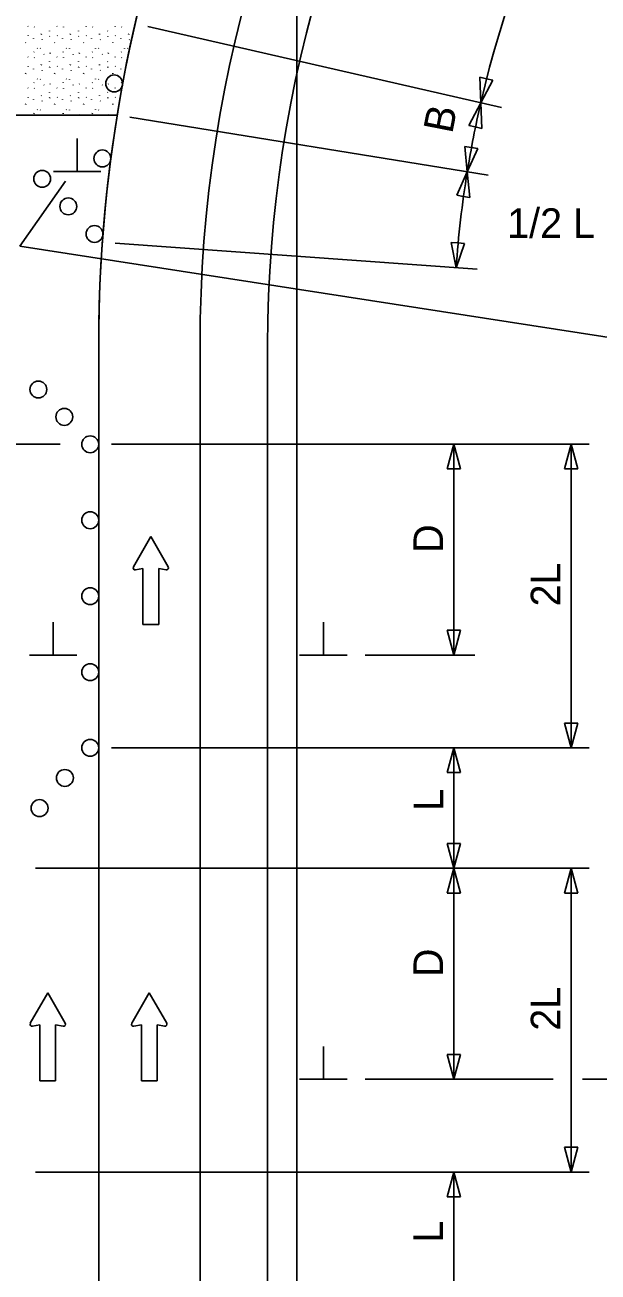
# Model space of a CAD drawing. Extents: x 16731 to 18475, y 7005 to 8303.
# Drawn here: x 16959.8 to 17095.5, y 7670.3 to 7965.9 of the extents above; entities that cross this region are included whole.
import ezdxf

# ---------------------------------------------------------------- set-up
doc = ezdxf.new("R2010")
doc.units = 0
for name, color, linetype in [('ALI_LEGAL_EX', 7, 'Continuous'), ('MT_SCRATCH_LEVEL_A', 7, 'Continuous'), ('MT_SCRATCH_LEVEL_E', 7, 'Continuous'), ('PAVT_EDGE_EX', 7, 'Continuous'), ('TRAFFIC_SIGNS_PR', 7, 'Continuous'), ('TYPICAL_TEXT_DIMEN_PR', 7, 'Continuous')]:
    doc.layers.add(name, color=color, linetype=linetype)

msp = doc.modelspace()

# ---------------------------------------------------------------- linework, layer by layer
at = {"layer": 'ALI_LEGAL_EX'}
for p, q in [((17024.17, 8303.41), (17024.17, 7485.27)), ((16977.23, 7389.77), (16977.23, 7890.11)), ((16977.23, 7307.34), (16977.23, 7890.11)), ((16977.23, 7307.34), (16977.23, 7890.11))]:
    msp.add_line(p, q, dxfattribs=at)
for points in [[(16977.23, 7890.11), (16977.23, 7879.92)], [(16977.23, 7679.92), (16977.23, 7704.92)]]:
    msp.add_lwpolyline(points, dxfattribs=at)
for start in [129.5666, 137.516]:
    msp.add_arc((17317.23, 7890.11), 340, start, 180, dxfattribs=at)
at = {"layer": 'MT_SCRATCH_LEVEL_A'}
for p, q in [((16960.45, 7965.61), (16960.51, 7965.53)), ((16961.98, 7965.47), (16962.04, 7965.39)), ((16965.55, 7964.55), (16965.6, 7964.47)), ((16967.34, 7965.61), (16967.39, 7965.53)), ((16968.87, 7965.47), (16968.92, 7965.39)), ((16972.44, 7964.55), (16972.49, 7964.47)), ((16974.23, 7965.61), (16974.28, 7965.53)), ((16975.76, 7965.47), (16975.81, 7965.39)), ((16979.33, 7964.55), (16979.38, 7964.47)), ((16981.12, 7965.61), (16981.17, 7965.53)), ((16982.65, 7965.47), (16982.7, 7965.39)), ((16959.88, 7961.65), (16959.94, 7961.76)), ((16960.5, 7963.4), (16960.55, 7963.32)), ((16961.78, 7962.82), (16961.8, 7962.71)), ((16963.63, 7963.68), (16963.68, 7963.8)), ((16963.81, 7962.48), (16963.87, 7962.4)), ((16965.59, 7963.15), (16965.65, 7963.27)), ((16966.77, 7961.65), (16966.82, 7961.76)), ((16967.39, 7963.4), (16967.44, 7963.32)), ((16968.67, 7962.82), (16968.69, 7962.71)), ((16970.51, 7963.68), (16970.57, 7963.8)), ((16970.7, 7962.48), (16970.75, 7962.4)), ((16972.48, 7963.15), (16972.53, 7963.27)), ((16973.66, 7961.65), (16973.71, 7961.76)), ((16974.28, 7963.4), (16974.33, 7963.32)), ((16975.56, 7962.82), (16975.57, 7962.71)), ((16977.4, 7963.68), (16977.45, 7963.8)), ((16977.59, 7962.48), (16977.64, 7962.4)), ((16979.37, 7963.15), (16979.42, 7963.27)), ((16980.55, 7961.65), (16980.6, 7961.76)), ((16981.17, 7963.4), (16981.22, 7963.32)), ((16982.45, 7962.82), (16982.46, 7962.71)), ((16984.29, 7963.68), (16984.34, 7963.8)), ((16984.48, 7962.48), (16984.53, 7962.4)), ((16960.45, 7958.32), (16960.51, 7958.25)), ((16961.9, 7959.45), (16961.96, 7959.57)), ((16962.67, 7960.41), (16962.72, 7960.33)), ((16963.41, 7960.38), (16963.46, 7960.3)), ((16964.27, 7959), (16964.33, 7958.92)), ((16965.72, 7959.15), (16965.78, 7959.27)), ((16967.34, 7958.32), (16967.39, 7958.25)), ((16968.79, 7959.45), (16968.84, 7959.57)), ((16969.56, 7960.41), (16969.61, 7960.33)), ((16970.29, 7960.38), (16970.35, 7960.3)), ((16971.16, 7959), (16971.21, 7958.92)), ((16972.61, 7959.15), (16972.66, 7959.27)), ((16974.23, 7958.32), (16974.28, 7958.25)), ((16975.68, 7959.45), (16975.73, 7959.57)), ((16976.44, 7960.41), (16976.5, 7960.33)), ((16977.18, 7960.38), (16977.23, 7960.3)), ((16978.05, 7959), (16978.1, 7958.92)), ((16979.5, 7959.15), (16979.55, 7959.27)), ((16981.12, 7958.32), (16981.17, 7958.25)), ((16982.57, 7959.45), (16982.62, 7959.57)), ((16983.33, 7960.41), (16983.38, 7960.33)), ((16984.07, 7960.38), (16984.12, 7960.3)), ((16960.5, 7956.12), (16960.55, 7956.04)), ((16961.78, 7955.54), (16961.8, 7955.42)), ((16961.98, 7958.18), (16962.04, 7958.11)), ((16963.63, 7956.4), (16963.68, 7956.51)), ((16965.55, 7957.27), (16965.6, 7957.19)), ((16965.59, 7955.86), (16965.65, 7955.98)), ((16967.39, 7956.12), (16967.44, 7956.04)), ((16968.67, 7955.54), (16968.69, 7955.42)), ((16968.87, 7958.18), (16968.92, 7958.11)), ((16970.51, 7956.4), (16970.57, 7956.51)), ((16972.44, 7957.27), (16972.49, 7957.19)), ((16972.48, 7955.86), (16972.53, 7955.98)), ((16974.28, 7956.12), (16974.33, 7956.04)), ((16975.56, 7955.54), (16975.57, 7955.42)), ((16975.76, 7958.18), (16975.81, 7958.11)), ((16977.4, 7956.4), (16977.45, 7956.51)), ((16979.33, 7957.27), (16979.38, 7957.19)), ((16979.37, 7955.86), (16979.42, 7955.98)), ((16981.17, 7956.12), (16981.22, 7956.04)), ((16982.45, 7955.54), (16982.46, 7955.42)), ((16982.65, 7958.18), (16982.7, 7958.11)), ((16959.88, 7954.36), (16959.94, 7954.48)), ((16962.67, 7953.13), (16962.72, 7953.05)), ((16963.41, 7953.1), (16963.46, 7953.02)), ((16963.81, 7955.2), (16963.87, 7955.12)), ((16966.77, 7954.36), (16966.82, 7954.48)), ((16969.56, 7953.13), (16969.61, 7953.05)), ((16970.29, 7953.1), (16970.35, 7953.02)), ((16970.7, 7955.2), (16970.75, 7955.12)), ((16973.66, 7954.36), (16973.71, 7954.48)), ((16976.44, 7953.13), (16976.5, 7953.05)), ((16977.18, 7953.1), (16977.23, 7953.02)), ((16977.59, 7955.2), (16977.64, 7955.12)), ((16980.55, 7954.36), (16980.6, 7954.48)), ((16960.45, 7951.04), (16960.51, 7950.96)), ((16961.9, 7952.17), (16961.96, 7952.28)), ((16961.98, 7950.9), (16962.04, 7950.82)), ((16964.27, 7951.72), (16964.33, 7951.64)), ((16965.55, 7949.98), (16965.6, 7949.9)), ((16965.72, 7951.87), (16965.78, 7951.99)), ((16967.34, 7951.04), (16967.39, 7950.96)), ((16968.79, 7952.17), (16968.84, 7952.28)), ((16968.87, 7950.9), (16968.92, 7950.82)), ((16971.16, 7951.72), (16971.21, 7951.64)), ((16972.44, 7949.98), (16972.49, 7949.9)), ((16972.61, 7951.87), (16972.66, 7951.99)), ((16974.23, 7951.04), (16974.28, 7950.96)), ((16975.68, 7952.17), (16975.73, 7952.28)), ((16975.76, 7950.9), (16975.81, 7950.82)), ((16978.05, 7951.72), (16978.1, 7951.64)), ((16979.33, 7949.98), (16979.38, 7949.9)), ((16979.5, 7951.87), (16979.55, 7951.99)), ((16981.12, 7951.04), (16981.17, 7950.96)), ((16982.57, 7952.17), (16982.62, 7952.28)), ((16982.65, 7950.9), (16982.7, 7950.82)), ((16959.88, 7947.08), (16959.94, 7947.19)), ((16960.5, 7948.83), (16960.55, 7948.75)), ((16961.78, 7948.25), (16961.8, 7948.14)), ((16963.63, 7949.11), (16963.68, 7949.23)), ((16963.81, 7947.91), (16963.87, 7947.83)), ((16965.59, 7948.58), (16965.65, 7948.7)), ((16966.77, 7947.08), (16966.82, 7947.19)), ((16967.39, 7948.83), (16967.44, 7948.75)), ((16968.67, 7948.25), (16968.69, 7948.14)), ((16970.51, 7949.11), (16970.57, 7949.23)), ((16970.7, 7947.91), (16970.75, 7947.83)), ((16972.48, 7948.58), (16972.53, 7948.7)), ((16973.66, 7947.08), (16973.71, 7947.19)), ((16974.28, 7948.83), (16974.33, 7948.75)), ((16975.56, 7948.25), (16975.57, 7948.14)), ((16977.4, 7949.11), (16977.45, 7949.23)), ((16977.59, 7947.91), (16977.64, 7947.83)), ((16979.37, 7948.58), (16979.42, 7948.7)), ((16980.55, 7947.08), (16980.6, 7947.19)), ((16981.17, 7948.83), (16981.22, 7948.75)), ((16949.15, 7944.52), (16981.61, 7944.52)), ((16949.15, 7944.52), (16981.61, 7944.52)), ((16961.9, 7944.88), (16961.96, 7945)), ((16962.67, 7945.84), (16962.72, 7945.76)), ((16963.41, 7945.81), (16963.46, 7945.73)), ((16965.72, 7944.58), (16965.78, 7944.7)), ((16968.79, 7944.88), (16968.84, 7945)), ((16969.56, 7945.84), (16969.61, 7945.76)), ((16970.29, 7945.81), (16970.35, 7945.73)), ((16972.61, 7944.58), (16972.66, 7944.7)), ((16975.68, 7944.88), (16975.73, 7945)), ((16976.44, 7945.84), (16976.5, 7945.76)), ((16977.18, 7945.81), (16977.23, 7945.73)), ((16979.5, 7944.58), (16979.55, 7944.7))]:
    msp.add_line(p, q, dxfattribs=at)
at = {"layer": 'MT_SCRATCH_LEVEL_E'}
for p, q in [((16989.55, 7844.68), (16985.44, 7837.44)), ((16989.55, 7844.68), (16985.44, 7837.44)), ((16993.7, 7837.44), (16989.55, 7844.68)), ((16993.7, 7837.44), (16989.55, 7844.68)), ((16985.92, 7836.76), (16987.7, 7837.07)), ((16985.92, 7836.76), (16987.7, 7837.07)), ((16987.7, 7837.07), (16987.7, 7823.82)), ((16987.7, 7837.07), (16987.7, 7823.82)), ((16991.44, 7823.82), (16991.44, 7837.07)), ((16991.44, 7837.07), (16993.22, 7836.76)), ((16991.44, 7823.82), (16991.44, 7837.07)), ((16991.44, 7837.07), (16993.22, 7836.76)), ((16987.7, 7823.82), (16991.44, 7823.82)), ((16987.7, 7823.82), (16991.44, 7823.82)), ((16965.15, 7736.5), (16961.04, 7729.26)), ((16965.15, 7736.5), (16961.04, 7729.26)), ((16969.3, 7729.26), (16965.15, 7736.5)), ((16969.3, 7729.26), (16965.15, 7736.5)), ((16989.21, 7736.5), (16985.1, 7729.26)), ((16989.21, 7736.5), (16985.1, 7729.26)), ((16993.35, 7729.26), (16989.21, 7736.5)), ((16993.35, 7729.26), (16989.21, 7736.5)), ((16961.53, 7728.58), (16963.3, 7728.89)), ((16961.53, 7728.58), (16963.3, 7728.89)), ((16963.3, 7728.89), (16963.3, 7715.63)), ((16963.3, 7728.89), (16963.3, 7715.63)), ((16967.04, 7715.63), (16967.04, 7728.89)), ((16967.04, 7728.89), (16968.82, 7728.58)), ((16967.04, 7715.63), (16967.04, 7728.89)), ((16967.04, 7728.89), (16968.82, 7728.58)), ((16985.58, 7728.58), (16987.36, 7728.89)), ((16985.58, 7728.58), (16987.36, 7728.89)), ((16987.36, 7728.89), (16987.36, 7715.63)), ((16987.36, 7728.89), (16987.36, 7715.63)), ((16991.1, 7715.63), (16991.1, 7728.89)), ((16991.1, 7728.89), (16992.87, 7728.58)), ((16991.1, 7715.63), (16991.1, 7728.89)), ((16991.1, 7728.89), (16992.87, 7728.58)), ((16963.3, 7715.63), (16967.04, 7715.63)), ((16963.3, 7715.63), (16967.04, 7715.63)), ((16987.36, 7715.63), (16991.1, 7715.63)), ((16987.36, 7715.63), (16991.1, 7715.63))]:
    msp.add_line(p, q, dxfattribs=at)
for centre, start, end in [((16985.85, 7837.22), 150.4248, 279.9638), ((16985.85, 7837.22), 150.4248, 279.9638), ((16993.29, 7837.22), 260.0362, 29.7731), ((16993.29, 7837.22), 260.0362, 29.7731), ((16961.45, 7729.03), 150.4248, 279.9638), ((16961.45, 7729.03), 150.4248, 279.9638), ((16968.89, 7729.04), 260.0362, 29.7731), ((16968.89, 7729.04), 260.0362, 29.7731), ((16985.5, 7729.03), 150.4248, 279.9638), ((16985.5, 7729.03), 150.4248, 279.9638), ((16992.94, 7729.04), 260.0362, 29.7731), ((16992.94, 7729.04), 260.0362, 29.7731)]:
    msp.add_arc(centre, 0.463, start, end, dxfattribs=at)
at = {"layer": 'PAVT_EDGE_EX'}
for p, q in [((17001.23, 7890.11), (17001.23, 7307.34)), ((17017.23, 7890.11), (17017.23, 7307.34))]:
    msp.add_line(p, q, dxfattribs=at)
for radius, start, end in [(316, 110.7433, 180), (300, 110.7433, 180), (300, 180, 180.00000277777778)]:
    msp.add_arc((17317.23, 7890.11), radius, start, end, dxfattribs=at)
at = {"layer": 'TRAFFIC_SIGNS_PR'}
for centre in [(16980.89, 7952.06), (16978.1, 7934.28), (16963.85, 7929.44), (16970.04, 7922.91), (16976.24, 7916.37), (16962.94, 7879.49), (16969.09, 7873), (16975.23, 7866.51), (16975.23, 7866.51), (16975.23, 7848.51), (16975.23, 7830.51), (16975.23, 7812.51), (16975.23, 7794.56), (16969.23, 7787.42), (16963.23, 7780.28)]:
    msp.add_circle(centre, 2, dxfattribs=at)
at = {"layer": 'TYPICAL_TEXT_DIMEN_PR'}
for p, q in [((17072.61, 7946.32), (16988.84, 7965.57)), ((17067.74, 7947.44), (17067.52, 7953.51)), ((17067.52, 7953.51), (17069.05, 7953.16)), ((17070.58, 7952.81), (17067.74, 7947.44)), ((17069.05, 7953.16), (17070.58, 7952.81)), ((17064.89, 7942.08), (17067.74, 7947.44)), ((17067.74, 7947.44), (17067.95, 7941.38)), ((17069.47, 7930.28), (16984.62, 7944.03)), ((17066.42, 7941.73), (17064.89, 7942.08)), ((17067.95, 7941.38), (17066.42, 7941.73)), ((16972.13, 7931.21), (16972.13, 7939)), ((17064.53, 7931.08), (17063.92, 7937.11)), ((17063.92, 7937.11), (17065.47, 7936.86)), ((17064.53, 7931.08), (17063.92, 7937.11)), ((17063.92, 7937.11), (17065.47, 7936.86)), ((17067.02, 7936.61), (17064.53, 7931.08)), ((17067.02, 7936.61), (17064.53, 7931.08)), ((17065.47, 7936.86), (17067.02, 7936.61)), ((17065.47, 7936.86), (17067.02, 7936.61)), ((16969.4, 7928.88), (16958.58, 7913.46)), ((16977.75, 7931.21), (16966.5, 7931.21)), ((17062.04, 7925.54), (17064.53, 7931.08)), ((17064.53, 7931.08), (17065.15, 7925.04)), ((17063.59, 7925.29), (17062.04, 7925.54)), ((17065.15, 7925.04), (17063.59, 7925.29)), ((17066.87, 7908.02), (16981.14, 7914.16)), ((17061.89, 7908.38), (17060.74, 7914.34)), ((17060.74, 7914.34), (17062.31, 7914.23)), ((17063.87, 7914.12), (17061.89, 7908.38)), ((17062.31, 7914.23), (17063.87, 7914.12)), ((16958.58, 7913.46), (17106.19, 7890.54)), ((16968.12, 7866.56), (16864.23, 7866.56)), ((17093.38, 7866.56), (16980.28, 7866.56)), ((17059.76, 7860.7), (17061.33, 7866.56)), ((17061.33, 7866.56), (17062.9, 7860.7)), ((17061.33, 7866.56), (17061.33, 7816.56)), ((17087.57, 7860.7), (17089.14, 7866.56)), ((17089.14, 7866.56), (17089.14, 7794.56)), ((17089.14, 7866.56), (17090.71, 7860.7)), ((17061.33, 7860.7), (17059.76, 7860.7)), ((17062.9, 7860.7), (17061.33, 7860.7)), ((17089.14, 7860.7), (17087.57, 7860.7)), ((17090.71, 7860.7), (17089.14, 7860.7)), ((16966.44, 7816.56), (16966.44, 7824.35)), ((17030.46, 7816.56), (17030.46, 7824.35)), ((17061.33, 7816.56), (17059.76, 7822.43)), ((17059.76, 7822.43), (17061.33, 7822.43)), ((17061.33, 7822.43), (17062.9, 7822.43)), ((17062.9, 7822.43), (17061.33, 7816.56)), ((16972.07, 7816.56), (16960.82, 7816.56)), ((17036.08, 7816.56), (17024.83, 7816.56)), ((17066.33, 7816.56), (17040.33, 7816.56)), ((17089.14, 7794.56), (17087.57, 7800.43)), ((17087.57, 7800.43), (17089.14, 7800.43)), ((17089.14, 7800.43), (17090.71, 7800.43)), ((17090.71, 7800.43), (17089.14, 7794.56)), ((16980.28, 7794.56), (17093.38, 7794.56)), ((17059.76, 7788.7), (17061.33, 7794.56)), ((17061.33, 7766), (17061.33, 7794.56)), ((17061.33, 7794.56), (17062.9, 7788.7)), ((17061.33, 7788.7), (17059.76, 7788.7)), ((17062.9, 7788.7), (17061.33, 7788.7)), ((17061.33, 7766), (17059.76, 7771.86)), ((17059.76, 7771.86), (17061.33, 7771.86)), ((17061.33, 7771.86), (17062.9, 7771.86)), ((17062.9, 7771.86), (17061.33, 7766)), ((17093.38, 7766), (16962.23, 7766)), ((17059.76, 7760.14), (17061.33, 7766)), ((17061.33, 7766), (17061.33, 7716)), ((17061.33, 7766), (17062.9, 7760.14)), ((17087.57, 7760.14), (17089.14, 7766)), ((17089.14, 7766), (17090.71, 7760.14)), ((17089.14, 7766), (17089.14, 7694)), ((17061.33, 7760.14), (17059.76, 7760.14)), ((17062.9, 7760.14), (17061.33, 7760.14)), ((17089.14, 7760.14), (17087.57, 7760.14)), ((17090.71, 7760.14), (17089.14, 7760.14)), ((17030.46, 7716), (17030.46, 7723.79)), ((17061.33, 7716), (17059.76, 7721.86)), ((17059.76, 7721.86), (17061.33, 7721.86)), ((17061.33, 7721.86), (17062.9, 7721.86)), ((17062.9, 7721.86), (17061.33, 7716)), ((17036.08, 7716), (17024.83, 7716)), ((17084.9, 7716), (17040.33, 7716)), ((17127.56, 7716), (17091.79, 7716)), ((17089.14, 7694), (17087.57, 7699.86)), ((17087.57, 7699.86), (17089.14, 7699.86)), ((17089.14, 7699.86), (17090.71, 7699.86)), ((17090.71, 7699.86), (17089.14, 7694)), ((16962.23, 7694), (17093.38, 7694)), ((17059.76, 7688.14), (17061.33, 7694)), ((17061.33, 7663.44), (17061.33, 7694)), ((17061.33, 7694), (17062.9, 7688.14)), ((17061.33, 7688.14), (17059.76, 7688.14)), ((17062.9, 7688.14), (17061.33, 7688.14))]:
    msp.add_line(p, q, dxfattribs=at)
for start, end in [(135.9481, 167.0592), (167.0592, 170.7929), (170.7929, 175.9084)]:
    msp.add_arc((17317.23, 7890.11), 256, start, end, dxfattribs=at)

# ---------------------------------------------------------------- texts
for s, rotation, p in [('B', 78.9226, (17060.96, 7939.96)), ('D', 90, (17058.77, 7840.78)), ('2L', 90, (17086.58, 7828.07)), ('L', 90, (17058.86, 7779.64)), ('D', 90, (17058.77, 7740.22)), ('2L', 90, (17086.58, 7727.5)), ('L', 90, (17058.77, 7677.29))]:
    msp.add_text(s, height=7, rotation=rotation, dxfattribs=at).set_placement(p)
msp.add_text('1/2 L', height=7, dxfattribs=at).set_placement((17073.97, 7915.45))

doc.saveas('drawing.dxf')
